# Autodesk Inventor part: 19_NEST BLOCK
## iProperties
Created: 2006-12
Part Number: 19_NEST BLOCK
Document SubType Name: Modeling
Designer: RDGodetteII
Material: Steel, High Strength Low Alloy
Mass: 2472.33 g
Surface Area: 388.175 cm^2
Volume: 315.349 cm^3
Density: 7.84 g/cm^3
Author: RDGodetteII
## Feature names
1. Extrusion1
2. Hole2
3. Rectangular Pattern2
